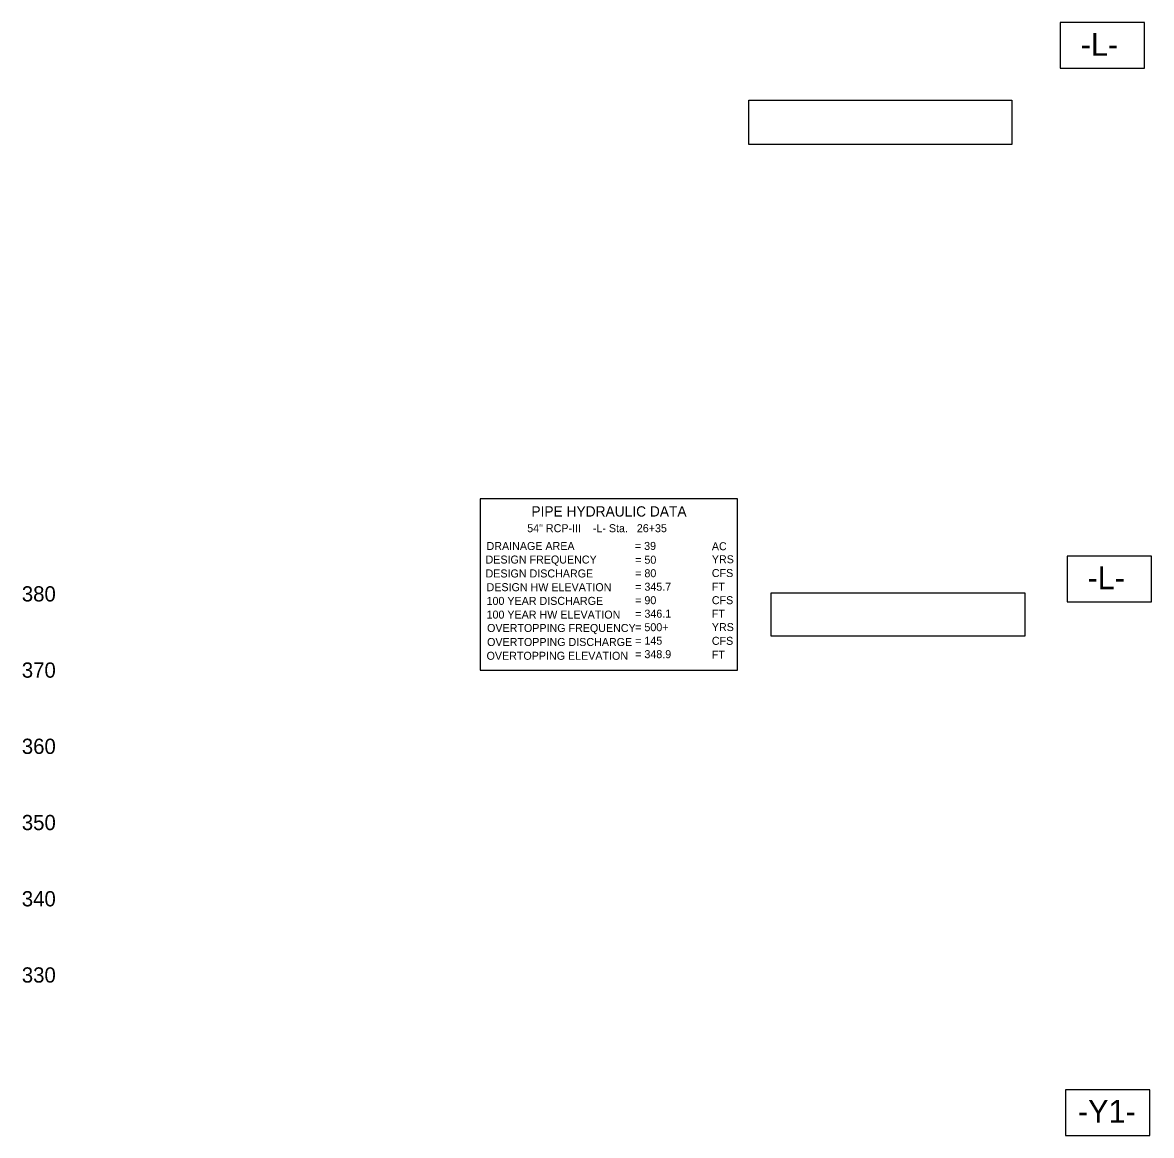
# Model space of a CAD drawing. Extents: x 2095765 to 2097235, y 866038 to 867018.
# Drawn here: x 2095765 to 2096506, y 866288 to 867018 of the extents above; entities that cross this region are included whole.
import ezdxf

# ---------------------------------------------------------------- set-up
doc = ezdxf.new("R2010")
doc.units = 0
for name, color, linetype in [('Exist Vertical Profile Vertical Axis Label', 7, 'Continuous'), ('Prop Grid Mask', 7, 'Continuous'), ('Prop PFL Pipe Hydraulic Data CELL', 7, 'Continuous')]:
    doc.layers.add(name, color=color, linetype=linetype)

msp = doc.modelspace()

# ---------------------------------------------------------------- linework, layer by layer
at = {"layer": 'Exist Vertical Profile Vertical Axis Label'}
for points in [[(2096445.96, 866988.32), (2096501.27, 866988.32), (2096501.27, 867018.32), (2096445.96, 867018.32)], [(2096241.61, 866967.41), (2096414.08, 866967.41), (2096414.08, 866938.28), (2096241.61, 866938.28)], [(2096450.43, 866638.32), (2096505.75, 866638.32), (2096505.75, 866668.32), (2096450.43, 866668.32)], [(2096256.22, 866644.27), (2096422.72, 866644.27), (2096422.72, 866615.85), (2096256.22, 866615.85)], [(2096449.45, 866288.32), (2096504.76, 866288.32), (2096504.76, 866318.32), (2096449.45, 866318.32)]]:
    msp.add_lwpolyline(points, close=True, dxfattribs=at)
at = {"layer": 'Prop Grid Mask'}
msp.add_lwpolyline([(2096065.3, 866593.51), (2096234.05, 866593.51), (2096234.05, 866706.01), (2096065.3, 866706.01)], close=True, dxfattribs=at)

# ---------------------------------------------------------------- texts
at = {"layer": 'Exist Vertical Profile Vertical Axis Label'}
for s, height, p in [('-L-', 15, (2096459.39, 866996.58)), ('-L-', 15, (2096463.86, 866646.58)), ('380', 10, (2095764.5, 866638.57)), ('370', 10, (2095764.5, 866588.57)), ('360', 10, (2095764.5, 866538.57)), ('350', 10, (2095764.5, 866488.57)), ('340', 10, (2095764.5, 866438.57)), ('330', 10, (2095764.5, 866388.57)), ('-Y1-', 15, (2096457.54, 866296.58))]:
    msp.add_text(s, height=height, dxfattribs=at).set_placement(p)
at = {"layer": 'Prop PFL Pipe Hydraulic Data CELL'}
for s, height, p in [('PIPE HYDRAULIC DATA', 6.7498, (2096098.9, 866694.27)), (' 54" RCP-III    -L- Sta.   26+35   ', 5.2497, (2096094.2, 866684.02)), ('DRAINAGE AREA', 5.2499, (2096069.48, 866672.33)), ('= 39     ', 5.25, (2096166.82, 866672.39)), ('AC', 5.25, (2096217.3, 866672.18)), ('DESIGN FREQUENCY', 5.2499, (2096068.81, 866663.45)), ('= 50 ', 5.25, (2096167, 866663.33)), ('YRS', 5.25, (2096217.3, 866663.63)), ('DESIGN DISCHARGE', 5.2499, (2096068.81, 866654.33)), ('= 80      ', 5.25, (2096167, 866654.48)), ('CFS', 5.25, (2096217.3, 866654.6)), ('DESIGN HW ELEVATION', 5.2499, (2096069.48, 866645.33)), ('= 345.7   ', 5.25, (2096167, 866645.63)), ('FT', 5.25, (2096217.3, 866645.63)), ('100 YEAR DISCHARGE', 5.2499, (2096069.48, 866636.33)), ('= 90      ', 5.25, (2096167, 866636.78)), ('CFS', 5.25, (2096217.3, 866636.78)), ('100 YEAR HW ELEVATION', 5.2499, (2096069.48, 866627.33)), ('= 346.1   ', 5.25, (2096167, 866627.93)), ('FT', 5.25, (2096217.3, 866627.93)), ('= 500+', 5.25, (2096167, 866619.08)), ('YRS', 5.25, (2096217.3, 866619.16)), ('OVERTOPPING FREQUENCY', 5.2499, (2096069.82, 866618.56)), ('OVERTOPPING DISCHARGE', 5.2499, (2096069.82, 866609.37)), ('= 145     ', 5.25, (2096167, 866610.23)), ('CFS', 5.25, (2096217.3, 866610.12)), ('OVERTOPPING ELEVATION', 5.2499, (2096069.48, 866600.33)), ('= 348.9   ', 5.25, (2096167, 866601.38)), ('FT', 5.25, (2096217.3, 866601.08))]:
    msp.add_text(s, height=height, dxfattribs=at).set_placement(p)

doc.saveas('drawing.dxf')
